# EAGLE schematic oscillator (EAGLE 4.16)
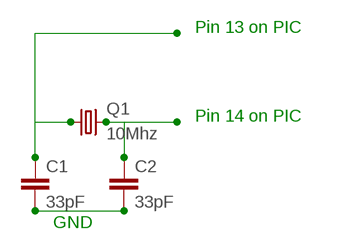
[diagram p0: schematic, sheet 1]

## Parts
C1  33pF  C-EU050-035X075  [C050-035X075]
C2  33pF  C-EU050-035X075  [C050-035X075]
Q1  10Mhz  CRYSTALHC49TL-H  [HC49TL-H]

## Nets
N$2: C2.1 Q1.2
N$3: C1.2 C2.2
N$5: C1.1 Q1.1

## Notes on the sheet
- Pin 13 on PIC
- Pin 14 on PIC
- GND

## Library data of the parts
C1 C2 = rcl:C-EU: CAPACITOR, European symbol
Q1 = crystal:CRYSTAL: CRYSTAL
